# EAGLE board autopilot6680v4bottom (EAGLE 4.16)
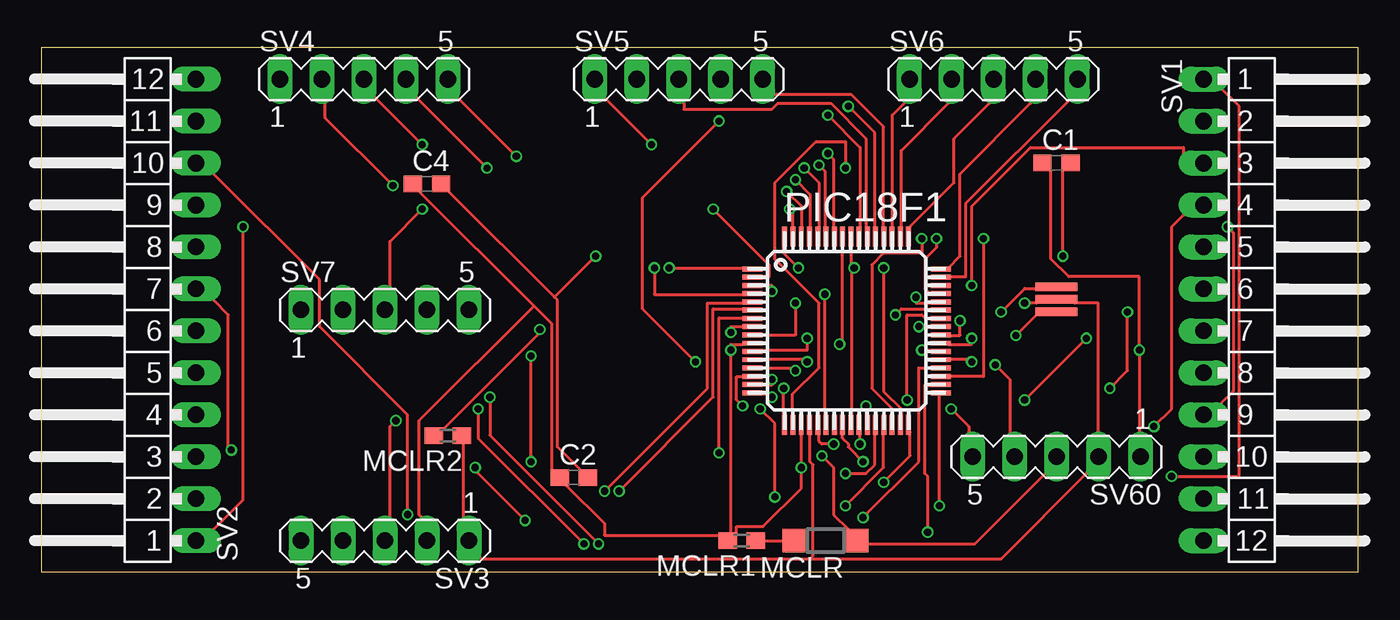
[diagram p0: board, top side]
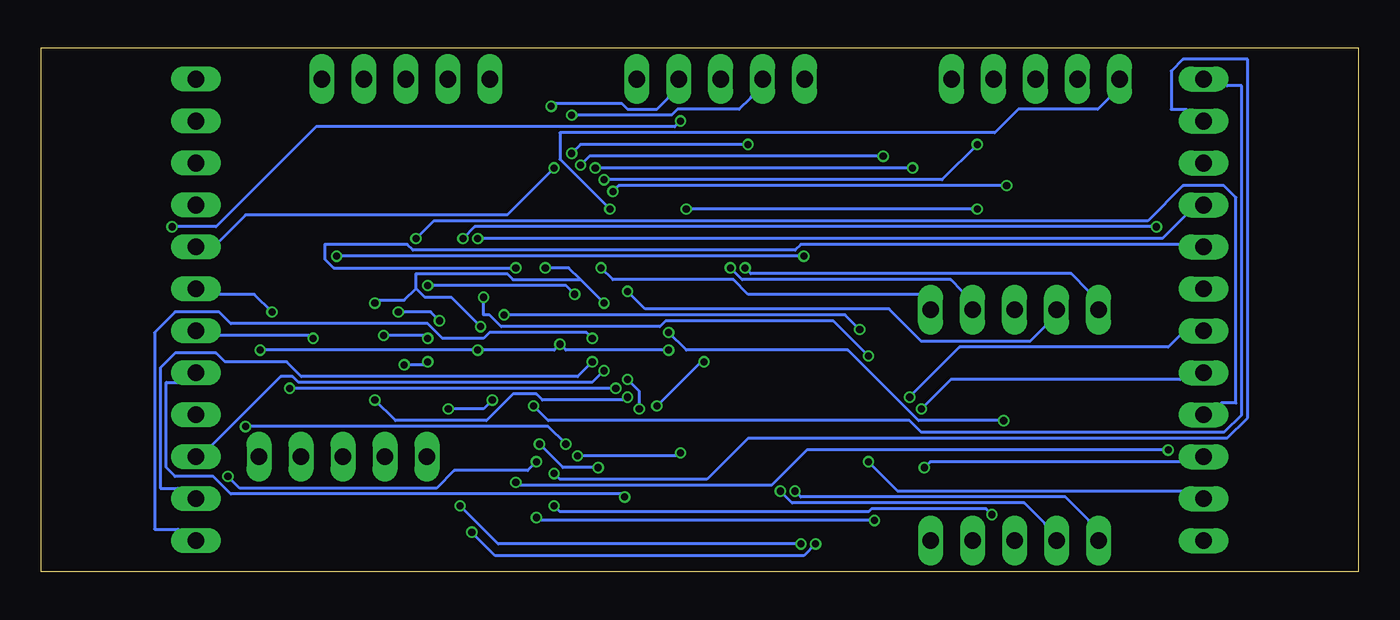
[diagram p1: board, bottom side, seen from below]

Size 79.68 x 31.74 mm. Coordinates in mm from the lower left corner, seen from the top.
Outline: 0,0 79.68,0 79.68,31.74 0,31.74 0,0
Copper layers (1*16): Top 0.035mm / dielectric 1.5mm / Bottom 0.035mm
Design rules "default": minimum track width 7mil, minimum drill 17mil, track to track 7mil, track to pad 7mil, pad to pad 7mil, via to via 7mil, smd to smd 7mil, copper to edge 10mil, drill to drill 8mil, minimum pad ring 7mil, minimum via ring 5mil, stop-mask expansion 4mil, vias tented up to drill 0mil, thermal gap 10mil

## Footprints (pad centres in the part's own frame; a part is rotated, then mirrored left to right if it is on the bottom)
C0603 = smd 1.1 x 1: 1 -0.85,0; 2 0.85,0
SOD123 = smd 1.4 x 1.4: A 1.9,0; C -1.9,0
R0603 = smd 1.1 x 1: 1 -0.85,0; 2 0.85,0
68TQFP10X10 = smd 1.2 x 0.3: 1 -1.89,5.02; 2 -1.89,4.52; 3 -1.89,4.02; 4 -1.89,3.52; 5 -1.89,3.02; 6 -1.89,2.52; 7 -1.89,2.02; 8 -1.89,1.52; 9 -1.89,1.02; 10 -1.89,0.52; 11 -1.89,0.02; 12 -1.89,-0.48; 13 -1.89,-0.98; 14 -1.89,-1.48; 15 -1.89,-1.98; 16 -1.89,-2.48; 33 9.51,-2.48; 34 9.51,-1.98; 35 9.51,-1.48; 36 9.51,-0.98; 37 9.51,-0.48; 38 9.51,0.02; 39 9.51,0.52; 40 9.51,1.02; 41 9.51,1.52; 42 9.51,2.02; 43 9.51,2.52; 44 9.51,3.02; 45 9.51,3.52; 46 9.51,4.02; 47 9.51,4.52; 48 9.51,5.02 | smd 0.3 x 1.2: 17 0.06,-4.43; 18 0.56,-4.43; 19 1.06,-4.43; 20 1.56,-4.43; 21 2.06,-4.43; 22 2.56,-4.43; 23 3.06,-4.43; 24 3.56,-4.43; 25 4.06,-4.43; 26 4.56,-4.43; 27 5.06,-4.43; 28 5.56,-4.43; 29 6.06,-4.43; 30 6.56,-4.43; 31 7.06,-4.43; 32 7.56,-4.43; 49 7.56,6.97; 50 7.06,6.97; 51 6.56,6.97; 52 6.06,6.97; 53 5.56,6.97; 54 5.06,6.97; 55 4.56,6.97; 56 4.06,6.97; 57 3.56,6.97; 58 3.06,6.97; 59 2.56,6.97; 60 2.06,6.97; 61 1.56,6.97; 62 1.06,6.97; 63 0.56,6.97; 64 0.06,6.97
MA12-1W = drill 1.016 long: 1 -13.97,0; 2 -11.43,0; 3 -8.89,0; 4 -6.35,0; 5 -3.81,0; 6 -1.27,0; 7 1.27,0; 8 3.81,0; 9 6.35,0; 10 8.89,0; 11 11.43,0; 12 13.97,0
MA05-1 = drill 1.016 long: 1 -5.08,0; 2 -2.54,0; 3 0,0; 4 2.54,0; 5 5.08,0
OSC = smd 2.54 x 0.508: GND 0,-0.635; IN1 0,-1.397; IN2 0,0.127

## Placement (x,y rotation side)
C1  [C0603]  61.43,24.76 0 top
C2  [C0603]  32.22,5.71 0 top
C4  [C0603]  23.33,23.49 0 top
MCLR  [SOD123]  47.46,1.9 180 top
MCLR1  10K  [R0603]  42.38,1.9 180 top
MCLR2  10K  [R0603]  24.6,8.25 180 top
PIC18F1  [68TQFP10X10]  44.92,13.33 0 top
SV1  [MA12-1W]  70.32,15.87 270 top
SV2  [MA12-1W]  9.36,15.87 90 top
SV3  [MA05-1]  20.79,1.9 180 top
SV4  [MA05-1]  19.52,29.84 0 top
SV5  [MA05-1]  38.57,29.84 0 top
SV6  [MA05-1]  57.62,29.84 0 top
SV7  [MA05-1]  20.79,15.87 0 top
SV60  [MA05-1]  61.43,6.98 180 top
U$2  OSCSMD  [OSC]  61.43,17.14 0 top

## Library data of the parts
C1 C2 C4 MCLR1 MCLR2 = rcl
MCLR = diode
PIC18F1 = pic18f6680plcc
SV1-SV7 SV60 = con-lstb
U$2 = OSCSMD

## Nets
+5V: C1.1 C2.1 C4.1 MCLR1.2 PIC18F1.10 PIC18F1.19 PIC18F1.26 PIC18F1.38 PIC18F1.57 SV3.2 SV60.1
GND: MCLR2.1 PIC18F1.9 PIC18F1.20 PIC18F1.25 PIC18F1.41 PIC18F1.56 SV3.1 SV60.2 U$2.GND
N$1: PIC18F1.42 SV60.5
N$2: PIC18F1.37 SV60.4
N$3: PIC18F1.24 SV1.1
N$4: SV1.2
N$5: PIC18F1.22 SV1.3
N$6: PIC18F1.21 SV1.4
N$7: PIC18F1.18 SV1.5
N$8: PIC18F1.17 SV1.6
N$9: PIC18F1.16 SV1.7
N$10: PIC18F1.15 SV1.8
N$11: PIC18F1.14 SV1.9
N$12: PIC18F1.13 SV1.10
N$13: PIC18F1.12 SV1.11
N$14: PIC18F1.11 SV1.12
N$15: PIC18F1.36 SV2.3
N$16: PIC18F1.35 SV2.4
N$17: PIC18F1.44 SV2.2
N$18: PIC18F1.34 SV2.5
N$19: PIC18F1.33 SV2.6
N$20: PIC18F1.32 SV2.7
N$21: PIC18F1.31 SV2.8
N$22: PIC18F1.45 SV2.1
N$23: PIC18F1.29 SV2.10
N$24: MCLR2.2 PIC18F1.43
N$25: PIC18F1.40 U$2.IN2
N$26: PIC18F1.39 U$2.IN1
N$27: PIC18F1.47 SV6.5
N$28: PIC18F1.48 SV6.4
N$29: PIC18F1.49 SV6.3
N$30: PIC18F1.50 SV6.2
N$31: PIC18F1.51 SV6.1
N$32: PIC18F1.52 SV5.5
N$33: PIC18F1.53 SV5.4
N$34: PIC18F1.54 SV5.3
N$35: PIC18F1.55 SV5.2
N$36: PIC18F1.58 SV5.1
N$37: PIC18F1.59 SV4.5
N$38: PIC18F1.60 SV4.4
N$39: PIC18F1.5 SV3.5
N$40: PIC18F1.61 SV4.3
N$41: PIC18F1.62 SV4.2
N$42: PIC18F1.63 SV4.1
N$43: PIC18F1.64 SV7.5
N$44: PIC18F1.2 SV7.3
N$45: PIC18F1.3 SV7.2
N$46: PIC18F1.4 SV7.1
N$47: MCLR.C PIC18F1.7 SV60.3
N$48: MCLR1.1 MCLR.A
N$49: PIC18F1.30 SV2.9
N$50: PIC18F1.46
N$51: PIC18F1.27 SV2.12
N$52: PIC18F1.28 SV2.11
N$54: PIC18F1.1 SV7.4
N$55: PIC18F1.6 SV3.4
N$56: PIC18F1.8 SV3.3
PE: C1.2 C2.2 C4.2

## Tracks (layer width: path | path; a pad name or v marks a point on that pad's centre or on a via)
+5V  (via drill 0.43)
  Top 0.178: C1.1 61.1,24.28 61.1,18.94 62.17,17.88 66.43,17.88 v66.43,13.43 66.43,8.45 SV60.1 | v48.3,13.79 48.48,13.97 48.48,19.83 PIC18F1.57 | v53.28,13.43 53.99,13.43 PIC18F1.38 | MCLR1.2 41.01,2.23 34.07,2.23 34.07,2.94 31.76,5.25 C2.1 30.87,6.14 30.87,15.03 29.81,16.1 | 29.81,16.1 22.87,23.03 C4.1 | PIC18F1.19 45.99,8.45 v45.99,6.32 45.99,5.08 43.67,2.76 42.07,2.76 42.07,2.23 MCLR1.2 | v49.54,7.74 49.54,8.45 PIC18F1.26 | PIC18F1.10 42.43,13.79 41.72,13.79 v41.72,13.43 41.72,2.23 MCLR1.2 | 29.81,16.1 22.87,9.16 22.87,3.48 23.05,3.3 SV3.2
  Bottom 0.178: v49.54,7.74 48.12,6.32 v45.99,6.32 | v41.72,13.43 47.94,13.43 v48.3,13.79 48.65,13.43 v53.28,13.43 v66.43,13.43
GND  (via drill 0.43)
  Top 0.178: v45.63,16.28 45.63,14.32 43.5,14.32 PIC18F1.9 | PIC18F1.56 49.01,19.83 49.01,18.59 v49.19,18.41 49.01,18.23 49.01,9.34 PIC18F1.25 | v53.1,14.85 53.99,14.85 PIC18F1.41 | MCLR2.1 25.54,7.92 25.54,3.3 SV3.1 26.61,0.81 46.52,0.81 | 46.52,0.81 46.7,0.99 46.7,6.5 46.52,6.67 46.52,8.45 PIC18F1.20 | 46.52,0.81 58.08,0.81 63.23,5.96 SV60.2 63.95,8.45 63.95,16.28 62.52,16.28 U$2.GND 60.21,16.28 v59.5,16.28
  Bottom 0.178: 47.05,17.7 47.77,18.41 v49.19,18.41 | 47.05,17.7 v45.63,16.28 | v53.1,14.85 54.88,16.63 56.48,16.63 57.01,17.16 | 57.01,17.16 57.01,18.05 51.5,18.05 51.14,17.7 47.05,17.7 | 57.01,17.16 57.72,16.45 59.32,16.45 v59.5,16.28
N$1  (via drill 0.43)
  Top 0.178: v52.39,10.41 52.39,15.57 53.28,15.57 53.45,15.39 53.99,15.39 PIC18F1.42 | v55.05,9.88 56.12,8.81 56.12,8.45 SV60.5
  Bottom 0.178: v52.39,10.41 52.92,9.88 v55.05,9.88
N$2  (via drill 0.43)
  Top 0.178: v56.3,12.72 56.3,12.9 54.88,12.9 PIC18F1.37 | v57.72,12.54 58.61,11.65 58.61,8.45 SV60.4
  Bottom 0.178: v56.3,12.72 56.48,12.54 v57.72,12.54
N$3  (via drill 0.43)
  Top 0.178: v49.72,6.67 48.83,7.56 48.83,7.74 48.48,8.1 48.48,8.45 PIC18F1.24 | v68.39,5.79 72.48,5.79 72.48,28.19 71.41,29.26 SV1.1
  Bottom 0.178: v49.72,6.67 50.25,6.14 54.7,6.14 55.77,5.08 67.68,5.08 v68.39,5.79
N$5  (via drill 0.43)
  Top 0.178: v47.41,16.81 47.41,9.34 PIC18F1.22 | v56.3,17.34 56.3,22.14 59.85,25.7 69.1,25.7 69.1,25.34 SV1.3
  Bottom 0.178: v47.41,16.81 47.94,17.34 v56.3,17.34
N$6  (via drill 0.43)
  Top 0.178: v47.94,7.74 47.23,7.74 47.05,7.92 47.05,8.45 PIC18F1.21 | v67.32,8.81 68.39,9.88 68.39,20.9 69.1,21.61 SV1.4
  Bottom 0.178: v47.94,7.74 49.01,8.81 v67.32,8.81
N$7  (via drill 0.43)
  Top 0.178: v48.65,24.45 48.65,26.05 46.88,26.05 44.39,23.57 44.39,18.94 47.05,16.28 47.05,12.37 45.45,10.77 45.45,9.34 PIC18F1.18
  Bottom 0.178: v48.65,24.45 51.5,21.61 67.32,21.61 68.92,20.01 SV1.5
N$8  (via drill 0.43)
  Top 0.178: v44.92,11.12 44.92,9.34 PIC18F1.17 | v64.66,11.12 65.72,12.19 v65.72,15.74
  Bottom 0.178: v44.92,11.12 v64.66,11.12 | v65.72,15.74 66.79,16.81 68.92,16.81 SV1.6
N$9  (via drill 0.43)
  Top 0.178: v44.21,10.59 44.21,10.77 43.5,10.77 PIC18F1.16 | v59.5,10.41 v63.23,14.14
  Bottom 0.178: v44.21,10.59 44.39,10.41 49.37,10.41 49.72,10.77 51.14,10.77 52.74,9.16 58.25,9.16 v59.5,10.41 | v63.23,14.14 63.41,14.32 68.92,14.32 SV1.7
N$10  (via drill 0.43)
  Top 0.178: v44.21,11.65 44.21,11.3 43.5,11.3 PIC18F1.15 | v43.5,9.88 44.39,8.99 v44.39,4.54
  Bottom 0.178: v44.21,11.65 43.5,10.94 v43.5,9.88 | v44.39,4.54 44.56,4.72 68.21,4.72 69.28,5.79 71.59,5.79 72.12,6.32 72.12,11.48 71.41,11.48 SV1.8
N$11  (via drill 0.43)
  Top 0.178: v42.43,10.05 42.07,10.41 42.07,11.83 42.43,11.83 PIC18F1.14 | v39.59,12.72 36.39,15.92 36.39,22.68 v41.01,27.3 | v71.77,20.9 72.12,20.54 72.12,10.94 71.41,10.23 SV1.9
  Bottom 0.178: v42.43,10.05 39.76,12.72 v39.59,12.72 | v41.01,27.3 41.36,26.94 63.06,26.94 69.1,20.9 v71.77,20.9
N$12  (via drill 0.43)
  Top 0.178: v45.63,12.19 45.63,12.37 43.5,12.37 PIC18F1.13
  Bottom 0.178: v45.63,12.19 46.34,11.48 64.12,11.48 64.48,11.83 65.19,11.83 69.46,7.56 SV1.10
N$13  (via drill 0.43)
  Top 0.178: v46.34,12.72 46.34,12.9 43.5,12.9 PIC18F1.12
  Bottom 0.178: v46.34,12.72 47.23,11.83 63.95,11.83 64.83,12.72 68.57,12.72 69.1,13.25 71.59,13.25 72.48,12.37 72.48,5.08 71.41,5.08 SV1.11
N$14  (via drill 0.43)
  Top 0.178: v46.34,14.14 46.34,13.43 43.5,13.43 PIC18F1.11
  Bottom 0.178: v46.34,14.14 46.7,14.5 52.56,14.5 52.92,14.14 55.41,14.14 56.3,15.03 68.21,15.03 68.92,15.74 71.59,15.74 72.83,14.5 72.83,2.59 71.41,2.59 SV1.12
N$15  (via drill 0.43)
  Top 0.178: v49.72,3.3 53.1,6.67 53.1,12.37 53.99,12.37 PIC18F1.36 | v29.27,3.12 26.25,6.14 v26.25,6.32
  Bottom 0.178: v49.72,3.3 49.54,3.12 v29.27,3.12 | v26.25,6.32 25.89,6.67 10.78,6.67 SV2.3
N$16  (via drill 0.43)
  Top 0.178: v57.01,20.19 57.01,11.83 54.88,11.83 PIC18F1.35
  Bottom 0.178: v57.01,20.19 55.94,21.25 12.74,21.25 10.61,23.39 8.12,23.39 7.4,22.68 7.4,10.23 8.29,10.23 SV2.4
N$17  (via drill 0.43)
  Top 0.178: v52.92,16.63 52.92,16.28 53.99,16.28 PIC18F1.44 | v29.63,6.67 v29.63,13.08
  Bottom 0.178: v52.92,16.63 52.92,15.57 52.56,15.57 51.85,14.85 42.25,14.85 41.9,15.21 31.76,15.21 v29.63,13.08 | v29.63,6.67 27.85,4.9 10.61,4.9 SV2.2
N$18  (via drill 0.43)
  Top 0.178: v53.63,2.41 53.63,5.79 53.45,5.96 53.45,11.3 53.99,11.3 PIC18F1.34 | v32.83,1.7 26.43,8.1 v26.43,9.88
  Bottom 0.178: v53.63,2.41 52.21,0.99 33.54,0.99 v32.83,1.7 | v26.43,9.88 24.65,11.65 10.78,11.65 SV2.5
N$19  (via drill 0.43)
  Top 0.178: v54.34,4.01 54.34,10.77 PIC18F1.33 | v33.72,1.7 27.14,8.28 v27.14,10.59
  Bottom 0.178: v54.34,4.01 52.03,1.7 v33.72,1.7 | v27.14,10.59 24.12,13.61 11.49,13.61 10.78,14.32 SV2.6
N$20  (via drill 0.43)
  Top 0.178: v50.96,5.43 52.56,7.03 52.56,8.45 PIC18F1.32 | v11.49,7.39 11.32,7.56 11.32,15.57 10.43,16.45 SV2.7
  Bottom 0.178: v50.96,5.43 50.79,5.25 35.5,5.25 33.36,7.39 v11.49,7.39
N$21  (via drill 0.43)
  Top 0.178: v50.96,18.41 50.96,10.94 52.03,9.88 52.03,9.34 PIC18F1.31
  Bottom 0.178: v50.96,18.41 61.99,18.41 62.52,18.94 62.52,19.83 57.54,19.83 57.19,19.48 34.07,19.48 33.72,19.83 10.78,19.83 SV2.8
N$22  (via drill 0.43)
  Top 0.178: v54.17,20.19 54.17,19.65 53.45,18.94 53.45,17.16 53.63,16.99 53.63,16.81 53.99,16.81 PIC18F1.45 | v12.21,20.9 12.21,4.36 10.43,2.59 SV2.1
  Bottom 0.178: v54.17,20.19 53.45,20.9 v12.21,20.9
N$23  (via drill 0.43)
  Top 0.178: v48.65,4.01 50.96,6.32 50.96,8.45 PIC18F1.29 | v22.16,3.48 22.16,9.52 16.83,14.85 16.83,17.7 10.43,24.1 SV2.10
  Bottom 0.178: v48.65,4.01 48.3,3.65 29.63,3.65 29.45,3.83 22.52,3.83 v22.16,3.48
N$24  (via drill 0.43)
  Top 0.178: v30.16,14.68 30.16,14.5 24.29,8.63 MCLR2.2 | v51.68,15.57 52.03,15.92 53.99,15.92 PIC18F1.43
  Bottom 0.178: v30.16,14.68 31.05,15.57 v51.68,15.57
N$25  (via drill 0.43)
  Top 0.178: v55.59,15.21 55.59,14.32 54.88,14.32 PIC18F1.40 | v58.08,15.74 59.5,17.16 60.21,17.16 U$2.IN2
  Bottom 0.178: v55.59,15.21 56.12,15.74 v58.08,15.74
N$26  (via drill 0.43)
  Top 0.178: v56.3,14.14 56.3,13.79 54.88,13.79 PIC18F1.39 | v58.97,14.32 60.21,15.57 U$2.IN1
  Bottom 0.178: v56.3,14.14 56.48,14.32 v58.97,14.32
N$27
  Top 0.178: PIC18F1.47 54.88,17.88 55.94,17.88 55.94,22.32 62.17,28.54 SV6.5
N$28
  Top 0.178: PIC18F1.48 54.88,18.41 55.59,19.12 55.59,24.1 59.85,28.37 SV6.4
N$29
  Top 0.178: PIC18F1.49 52.56,20.9 55.23,23.57 55.23,26.23 57.37,28.37 SV6.3
N$30
  Top 0.178: PIC18F1.50 52.03,20.9 52.03,25.52 54.88,28.37 SV6.2
N$31
  Top 0.178: PIC18F1.51 51.5,20.9 51.5,27.66 52.21,28.37 SV6.1
N$32
  Top 0.178: PIC18F1.52 50.96,20.9 50.96,26.94 49.01,28.9 44.39,28.9 SV5.5
N$33  (via drill 0.43)
  Top 0.178: v48.83,28.19 50.43,26.59 50.43,20.9 PIC18F1.53
  Bottom 0.178: v48.83,28.19 48.65,28.37 44.56,28.37 44.21,28.01 42.43,28.01 41.72,28.72 SV5.4
N$34
  Top 0.178: PIC18F1.54 49.9,20.9 49.9,26.23 47.77,28.37 44.56,28.37 44.21,28.01 38.88,28.01 38.88,28.37 SV5.3
N$35  (via drill 0.43)
  Top 0.178: v47.59,27.66 49.54,25.7 49.54,20.9 PIC18F1.55
  Bottom 0.178: v47.59,27.66 41.54,27.66 41.19,28.01 37.45,28.01 36.74,28.72 SV5.2
N$36  (via drill 0.43)
  Top 0.178: v47.59,25.34 47.94,24.99 47.94,20.9 PIC18F1.58 | v36.92,25.88 34.07,28.72 SV5.1
  Bottom 0.178: v47.59,25.34 47.05,25.88 v36.92,25.88
N$37  (via drill 0.43)
  Top 0.178: v47.05,24.63 47.41,24.28 47.41,20.9 PIC18F1.59 | v28.74,25.17 25.18,28.72 SV4.5
  Bottom 0.178: v47.05,24.63 46.52,25.17 v28.74,25.17
N$38  (via drill 0.43)
  Top 0.178: v46.16,24.45 47.05,23.57 47.05,20.9 PIC18F1.60 | v26.96,24.45 22.7,28.72 SV4.4
  Bottom 0.178: v26.96,24.45 v46.16,24.45
N$39  (via drill 0.43)
  Top 0.178: v34.07,4.9 40.3,11.12 40.3,16.28 42.43,16.28 PIC18F1.5
  Bottom 0.178: v34.07,4.9 33.72,4.54 17.72,4.54 16.29,3.12 SV3.5
N$40  (via drill 0.43)
  Top 0.178: v45.63,23.74 46.52,22.86 46.52,20.9 PIC18F1.61 | v23.05,25.88 20.21,28.72 SV4.3
  Bottom 0.178: v45.63,23.74 25.18,23.74 v23.05,25.88
N$41  (via drill 0.43)
  Top 0.178: v45.1,23.03 45.99,22.14 45.99,20.9 PIC18F1.62 | v21.27,23.39 17.18,27.48 17.18,28.37 SV4.2
  Bottom 0.178: v45.1,23.03 44.74,23.39 v21.27,23.39
N$42  (via drill 0.43)
  Top 0.178: v45.28,21.97 45.45,21.79 45.45,20.9 PIC18F1.63
  Bottom 0.178: v45.28,21.97 48.3,24.99 48.3,26.59 21.98,26.59 20.56,28.01 15.76,28.01 15.05,28.72 SV4.1
N$43  (via drill 0.43)
  Top 0.178: v45.81,18.41 44.92,19.3 44.92,19.83 PIC18F1.64
  Bottom 0.178: v45.81,18.41 45.1,17.7 37.81,17.7 36.92,16.81 26.61,16.81 SV7.5
N$44  (via drill 0.43)
  Top 0.178: v40.65,21.97 44.03,18.59 44.03,17.88 43.5,17.88 PIC18F1.2 | v23.05,21.97 21.09,20.01 21.09,17.34 SV7.3
  Bottom 0.178: v23.05,21.97 v40.65,21.97
N$45  (via drill 0.43)
  Top 0.178: v44.21,16.99 44.21,17.34 43.5,17.34 PIC18F1.3
  Bottom 0.178: v44.21,16.99 43.14,15.92 28.38,15.92 26.43,13.97 19.85,13.97 18.96,14.85 SV7.2
N$46  (via drill 0.43)
  Top 0.178: v37.1,18.41 37.1,16.81 42.43,16.81 PIC18F1.4
  Bottom 0.178: v37.1,18.41 36.74,18.05 17.36,18.05 16.29,16.99 SV7.1
N$47  (via drill 0.43)
  Top 0.178: v41.01,7.21 41.01,15.39 42.43,15.39 PIC18F1.7 | v47.23,7.03 47.94,6.32 47.94,3.48 48.83,2.59 MCLR.C 49.9,1.7 56.48,1.7 60.74,5.96 SV60.3
  Bottom 0.178: v41.01,7.21 41.19,7.03 v47.23,7.03
N$48
  Top 0.178: MCLR1.1 43.67,1.88 44.92,1.88 MCLR.A
N$49  (via drill 0.43)
  Top 0.178: v53.28,20.19 53.28,19.3 50.96,19.3 50.25,18.59 50.25,11.12 51.5,9.88 51.5,9.34 PIC18F1.30
  Bottom 0.178: v53.28,20.19 11.85,20.19 10.43,21.61 SV2.9
N$51  (via drill 0.43)
  Top 0.178: v49.9,10.05 49.9,9.34 PIC18F1.27
  Bottom 0.178: v49.9,10.05 49.01,9.16 27.14,9.16 26.43,8.45 8.12,8.45 7.05,9.52 7.05,29.43 7.94,29.43 SV2.12
N$52  (via drill 0.43)
  Top 0.178: v48.65,5.96 49.9,5.96 50.43,6.5 50.43,8.45 PIC18F1.28
  Bottom 0.178: v48.65,5.96 48.3,5.61 39.41,5.61 36.92,8.1 7.94,8.1 6.69,9.34 6.69,31.03 10.61,31.03 11.32,30.32 11.32,28.01 10.43,28.01 SV2.11
N$54  (via drill 0.43)
  Top 0.178: v37.99,18.41 42.43,18.41 PIC18F1.1
  Bottom 0.178: v37.99,18.41 37.27,17.7 24.65,17.7 23.94,16.99 SV7.4
N$55  (via drill 0.43)
  Top 0.178: v34.96,4.9 40.65,10.59 40.65,15.92 42.43,15.92 PIC18F1.6
  Bottom 0.178: v34.96,4.9 34.25,4.19 20.21,4.19 18.96,2.94 SV3.4
N$56  (via drill 0.43)
  Top 0.178: v41.72,14.5 41.72,14.85 42.43,14.85 PIC18F1.8 | v21.45,9.16 21.09,8.81 21.09,3.3 SV3.3
  Bottom 0.178: v41.72,14.5 40.65,13.43 30.87,13.43 26.61,9.16 v21.45,9.16
PE  (via drill 0.43)
  Top 0.178: 31.05,16.63 24.65,23.03 C4.2 | 31.05,16.63 31.23,16.45 31.23,7.56 32.65,6.14 C2.2 | v61.81,19.12 61.81,24.28 C1.2 | 31.05,16.63 v33.54,19.12
  Bottom 0.178: v33.54,19.12 v61.81,19.12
